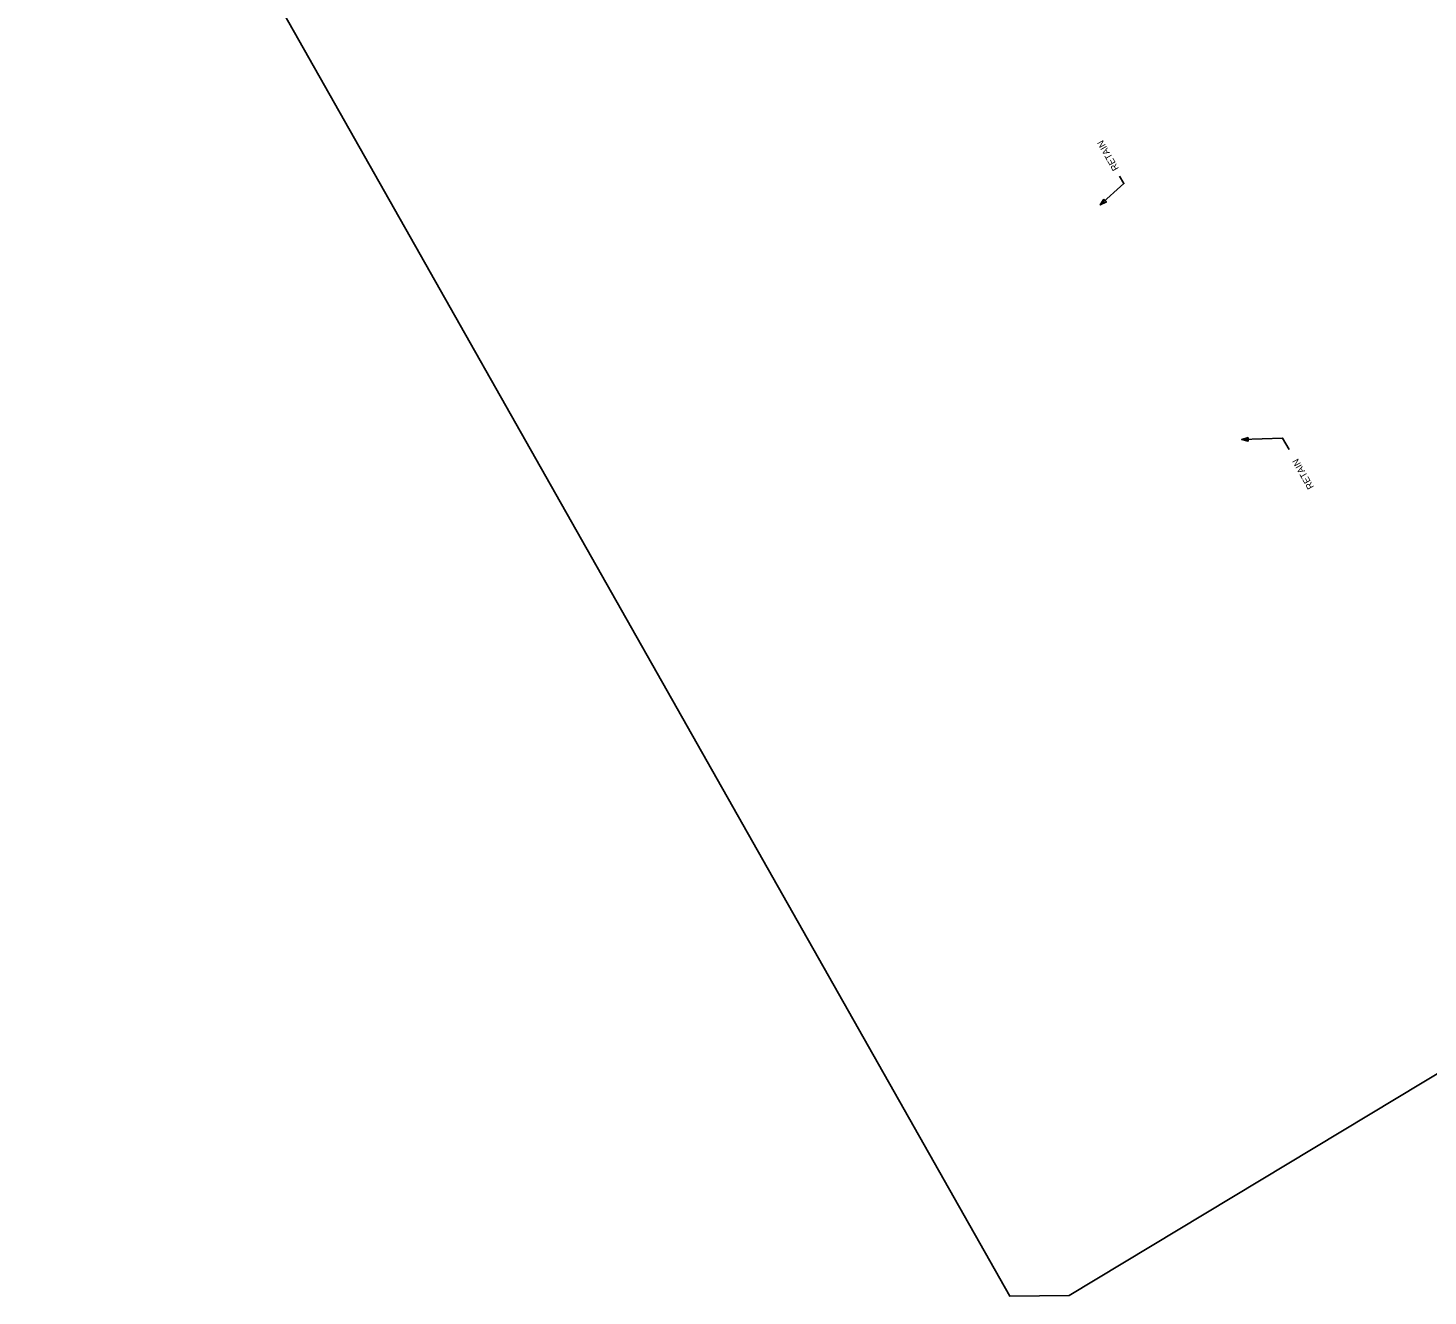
# Model space of a CAD drawing. Extents: x 1612558 to 1614658, y 1085653 to 1087522.
# Drawn here: x 1612577 to 1613608, y 1085653 to 1086587 of the extents above; entities that cross this region are included whole.
import ezdxf

# ---------------------------------------------------------------- set-up
doc = ezdxf.new("R2010")
doc.units = 0
doc.layers.add('Exist Structure Minor Footbridge Terminator', color=7, linetype='Continuous')
doc.layers.add('RD_HC_Data', color=7, linetype='Continuous')

msp = doc.modelspace()

# ---------------------------------------------------------------- linework, layer by layer
at = {"layer": 'Exist Structure Minor Footbridge Terminator'}
for points in [[(1613380.8, 1086478.3), (1613384, 1086472.7), (1613366.6, 1086457)], [(1613505.7, 1086276.7), (1613500.9, 1086285.2), (1613470.8, 1086284.1)]]:
    msp.add_lwpolyline(points, dxfattribs=at)
for points in [[(1613369.3, 1086461.2), (1613366.6, 1086457), (1613371.1, 1086459.2)], [(1613475.6, 1086285.6), (1613470.8, 1086284.1), (1613475.7, 1086283)]]:
    msp.add_lwpolyline(points, close=True, dxfattribs=at)
at = {"layer": 'RD_HC_Data'}
msp.add_lwpolyline([(1613343.7, 1085653.3), (1614126.4, 1086125), (1613415.2, 1087379), (1613116.7, 1087245.1), (1612843.1, 1087121.9), (1612576.5, 1087002), (1612672.7, 1086832.1), (1612642.4, 1086814.9), (1613299.9, 1085652.9)], close=True, dxfattribs=at)
msp.add_lwpolyline([(1613343.7, 1085653.3), (1614126.4, 1086125), (1613415.2, 1087379), (1613116.7, 1087245.1), (1612843.1, 1087121.9), (1612576.5, 1087002), (1612672.7, 1086832.1), (1612642.4, 1086814.9), (1613299.9, 1085652.9)], close=True, dxfattribs=at)
msp.add_lwpolyline([(1613343.7, 1085653.3), (1614126.4, 1086125), (1613415.2, 1087379), (1613116.7, 1087245.1), (1612843.1, 1087121.9), (1612576.5, 1087002), (1612672.7, 1086832.1), (1612642.4, 1086814.9), (1613299.9, 1085652.9)], close=True, dxfattribs=at)
msp.add_lwpolyline([(1613343.7, 1085653.3), (1614126.4, 1086125), (1613415.2, 1087379), (1613116.7, 1087245.1), (1612843.1, 1087121.9), (1612576.5, 1087002), (1612672.7, 1086832.1), (1612642.4, 1086814.9), (1613299.9, 1085652.9)], close=True, dxfattribs=at)
msp.add_lwpolyline([(1613343.7, 1085653.3), (1614126.4, 1086125), (1613415.2, 1087379), (1613116.7, 1087245.1), (1612843.1, 1087121.9), (1612576.5, 1087002), (1612672.7, 1086832.1), (1612642.4, 1086814.9), (1613299.9, 1085652.9)], close=True, dxfattribs=at)
msp.add_lwpolyline([(1613343.7, 1085653.3), (1614126.4, 1086125), (1613415.2, 1087379), (1613116.7, 1087245.1), (1612843.1, 1087121.9), (1612576.5, 1087002), (1612672.7, 1086832.1), (1612642.4, 1086814.9), (1613299.9, 1085652.9)], close=True, dxfattribs=at)
msp.add_lwpolyline([(1613343.7, 1085653.3), (1614126.4, 1086125), (1613415.2, 1087379), (1613116.7, 1087245.1), (1612843.1, 1087121.9), (1612576.5, 1087002), (1612672.7, 1086832.1), (1612642.4, 1086814.9), (1613299.9, 1085652.9)], close=True, dxfattribs=at)

# ---------------------------------------------------------------- texts
at = {"layer": 'Exist Structure Minor Footbridge Terminator'}
for p in [(1613380.5, 1086483.9), (1613524.2, 1086249.2)]:
    msp.add_text('RETAIN', height=5, rotation=119.5163, dxfattribs=at).set_placement(p)

doc.saveas('drawing.dxf')
